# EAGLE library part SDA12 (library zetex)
DIODE ARRAY
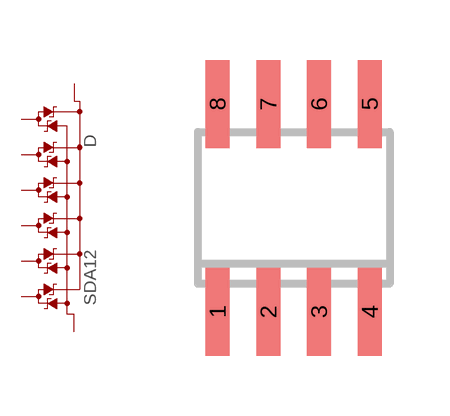
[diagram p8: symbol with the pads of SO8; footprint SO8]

Designator prefix D

## SDA12 (OC_FARNELL: 9802282; OC_NEWARK: unknown)  [SO8]
1  V+  pas
2  D01  pas
3  D02  pas
4  D03  pas
5  V-  pas
6  D04  pas
7  D05  pas
8  D06  pas

## Footprint SO8 (pad centres in mm)
SMALL OUTLINE INTEGRATED CIRCUIT
smd 0.6 x 2.2: 1 -1.905,-2.6; 2 -0.635,-2.6; 3 0.635,-2.6; 4 1.905,-2.6; 5 1.905,2.6; 6 0.635,2.6; 7 -0.635,2.6; 8 -1.905,2.6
